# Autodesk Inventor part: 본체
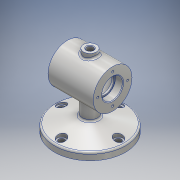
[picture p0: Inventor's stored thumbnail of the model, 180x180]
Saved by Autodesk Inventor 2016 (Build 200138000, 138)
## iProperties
Created: 2018-12
Part Number: 본체
Material: 알루미늄 6061
Document SubType Name: Modeling
Designer: 605-17
Density: 2.7 g/cm^3
Appearance: 알루미늄 - 평지
Mass: 685.089 g
Surface Area: 555.496 cm^2
Volume: 253.737 cm^3
Author: 605-17
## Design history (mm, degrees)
sketch "스케치1"
  geometry: C1 r 55 at (0, 0); 1 further point
  constraints: 1 centre point, 1 coincident
  dimensions: "d0" = 110 diameter of C1
extrude "돌출1" new body sketch "스케치1" distance "d1" = 11; taper "d2" = 0 deg
sketch "스케치2"
  geometry: L1 (0, 11)-(0, 22.522); L2 (0, 22.522)-(-12, 22.522); L3 (-12, 22.522)-(-55, 11); L4 (-55, 11)-(0, 11); L5 (-55, 0)-(-55, 11) reference; L6 (55, 11)-(-55, 11) reference; 2 further points
  constraints: 8 end point, 1 collinear, 1 midpoint, 1 perpendicular, 1 vertical, 1 vertical alignment
  dimensions: "d3" = 75 deg angle of L5 L3; "d4" = 12 distance of L2.end L1.end
revolve "회전1" sketch "스케치2" stored, may be unused: angle "d5" = 90 deg
sketch "스케치4"
  geometry: C1 r 30 at (0, 75); 1 further point
  constraints: 1 centre point, 1 vertical alignment
  dimensions: "d6" = 75 distance of point (0, 0) C1.centre; "d7" = 60 diameter of C1
extrude "돌출2" join sketch "스케치4" stored distance "d8" = 70; taper "d9" = 0 deg
sketch "스케치5"
  geometry: C1 r 12 at (0, 0); 1 further point
  constraints: 1 centre point, 1 coincident
  dimensions: "d10" = 24 diameter of C1
extrude "돌출3" join sketch "스케치5" stored distance "d11" = 70; taper "d12" = 0 deg; dims "d38" = 45 deg
sketch "스케치6"
  geometry: L1 (-35, 91)-(-23, 91); L2 (-23, 91)-(-23, 89); L3 (-23, 89)-(-20, 89); L4 (-20, 89)-(-20, 97); L5 (-17, 100)-(17, 100); L6 (20, 97)-(20, 89); L7 (20, 89)-(23, 89); L8 (23, 89)-(23, 91); L9 (23, 91)-(35, 91); L10 (35, 91)-(35, 75); L11 (35, 75)-(-35, 75); L12 (-35, 91)-(-35, 75); L13 (-35, 105)-(-35, 45) reference; A1 r 3 centre (-17, 97) between (-17, 100) and (-20, 97); A2 r 3 centre (17, 97) between (20, 97) and (17, 100); 3 further points
  constraints: 24 end point, 10 perpendicular, 6 point on line, 4 point on circle, 4 tangent, 2 centre point, 1 equal radius, 1 horizontal, 1 midpoint
  dimensions: "d13" = 16 distance of L1.start L11.end; "d14" = 14 distance from line of L11.end L3; "d15" = 12 distance of L1.start L1.end; "d16" = 3 distance of L2.end L3.end; "d17" = 16 distance from line of L10.end L9 (derived); "d18" = 14 distance from line of L10.end L7; "d19" = 3 distance of L6.end L7.end; "d20" = 12 distance of L8.end L9.end; "d21" = 40 distance of point (-20, 100) point (20, 100); "d22" = 25 distance from line of L10.end L5; "d24" = 3 radius of A1
revolve "회전2" sketch "스케치6" stored, may be unused: angle "d23" = 90 deg
chamfer "모따기1" distance "d25" = 1; stored, may be unused: second distance "d26" = 2, angle "d27" = 45 deg
node "작업 평면2"
sketch "스케치8"
  geometry: C1 r 10 at (0, 0); 1 further point
  constraints: 1 centre point, 1 coincident
  dimensions: "d29" = 20 diameter of C1
extrude "돌출4" join sketch "스케치8" stored distance "d30" = 70; taper "d31" = 0 deg
sketch "스케치9"
  geometry: C1 r 5 at (0, 0); 1 further point
  constraints: 1 centre point, 1 coincident
  dimensions: "d32" = 10 diameter of C1
extrude "돌출5" cut sketch "스케치9" distance "d33" = 30; taper "d34" = 0 deg
fillet "모깎기1" dims "d35" = 0.3
chamfer "모따기2" distance "d36" = 1; stored, may be unused: second distance "d37" = 2, angle "d38" = 45 deg
sketch "스케치10"
  geometry: C1 r 30 at (0, 0) reference; A1 r 23 centre (0, 0) between (-23, 0) and (23, 0); 3 further points
  constraints: 4 point on circle, 2 horizontal alignment, 2 vertical alignment, 1 centre point, 1 coincident
  dimensions: "d39" = 46 diameter of A1
hole "구멍1" sketch "스케치10" at (-23, 0), (23, 0), (0, -23), (0, 23) diameter "d42" = 3.242; stored, may be unused: countersink angle "d46" = 90 deg, drill point angle "d48" = 118 deg; dims "d43" = 8, "d44" = 4, "d45" = 2, "d47" = 10
node "작업 평면3"
sketch "스케치11" dims "d49" = 88
  geometry: C1 r 4.5 at (0, 44); 2 further points
  constraints: 2 vertical alignment, 1 centre point, 1 coincident, 2 other
  dimensions: "d50" = 9 diameter of C1
extrude "돌출6" cut sketch "스케치11" distance "d51" = 10; taper "d52" = 0 deg
sketch "스케치12"
  geometry: C1 r 4.5 at (0, 0) reference; C2 r 7 at (0, 0); 1 further point
  constraints: 1 centre point, 1 coincident
  dimensions: "d53" = 14 diameter of C2
extrude "돌출7" cut sketch "스케치12" distance "d54" = 10; taper "d55" = 0 deg
fillet "모깎기2" dims "d59" = 3
fillet "모깎기3" dims "d60" = 3
node "작업 평면5"
sketch "스케치14"
  geometry: L1 (-35, 105)-(-35, 45) reference; L2 (35, 105)-(-35, 105) reference; 2 further points
  constraints: 1 other
  dimensions: "d63" = 35 distance from line of point (0, 75) L1; "d64" = 30 distance from line of point (0, 75) L2
feature "엠보싱1" sketch "스케치14" dims "d10" = 24, "d65" = 0.5, "d66" = 0
node "솔리드1"
mirror "대칭1"
pattern_circular "원형 패턴1" dims angle "d57" = 360 deg
other parameters: "d28" = 112, "d62" = 54.5
